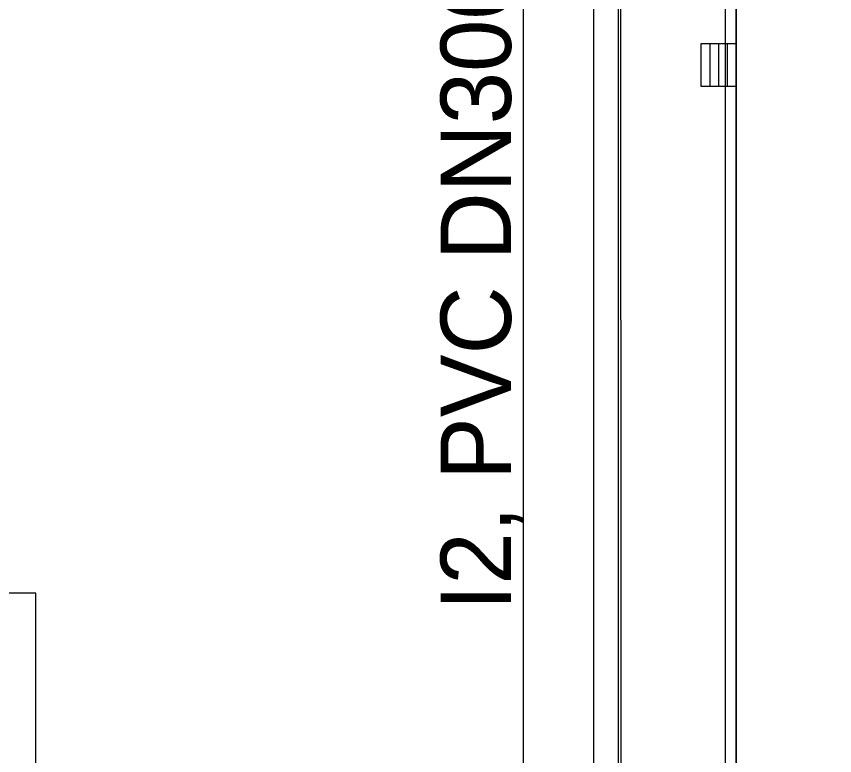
# Model space of a CAD drawing. Extents: x -264234 to -263604, y -1242346 to -1242049.
# Drawn here: x -263832.36 to -263809.12, y -1242205 to -1242184 of the extents above; entities that cross this region are included whole.
import ezdxf

# ---------------------------------------------------------------- set-up
doc = ezdxf.new("R2010")
doc.units = 0
for name, color, linetype in [('KFA_DAZDOVA_KANALIZACIA_vetva_I', 7, 'Continuous'), ('KFA_DAZDOVA_KANALIZACIA_vetva_I_popis', 7, 'Continuous'), ('KFA_SITUACIA_DSP', 7, 'Continuous')]:
    doc.layers.add(name, color=color, linetype=linetype)

msp = doc.modelspace()

# ---------------------------------------------------------------- linework, layer by layer
at = {"layer": 'KFA_DAZDOVA_KANALIZACIA_vetva_I'}
msp.add_lwpolyline([(-263814.907, -1242107.856), (-263815.198, -1242164.443), (-263815.189, -1242220.791), (-263852.152, -1242220.736), (-263888.701, -1242220.786), (-263906.731, -1242239.259)], dxfattribs=at)
at = {"layer": 'KFA_SITUACIA_DSP'}
for p, q in [((-263815.263, -1242164.687), (-263815.263, -1242220.396)), ((-263811.918, -1242184.782), (-263812.918, -1242184.782)), ((-263812.918, -1242184.782), (-263812.918, -1242185.982)), ((-263812.668, -1242184.782), (-263812.668, -1242185.982)), ((-263812.418, -1242184.782), (-263812.418, -1242185.982)), ((-263812.168, -1242184.782), (-263812.168, -1242185.982)), ((-263812.918, -1242185.982), (-263811.918, -1242185.982))]:
    msp.add_line(p, q, dxfattribs=at)
for points in [[(-263816.02, -1242224.432), (-263811.918, -1242220.33), (-263811.918, -1242108.434), (-263816.02, -1242104.332), (-263887.916, -1242104.332), (-263892.018, -1242108.434), (-263892.018, -1242147.332), (-263893.618, -1242147.332), (-263893.618, -1242162.382), (-263894.718, -1242162.382), (-263894.718, -1242166.382), (-263893.618, -1242166.382), (-263893.618, -1242181.432), (-263892.018, -1242181.432), (-263892.018, -1242220.33), (-263887.916, -1242224.432)], [(-263816.144, -1242224.132), (-263812.218, -1242220.206), (-263812.218, -1242108.558), (-263816.144, -1242104.632), (-263887.792, -1242104.632), (-263891.718, -1242108.558), (-263891.718, -1242147.632), (-263893.318, -1242147.632), (-263893.318, -1242162.682), (-263894.418, -1242162.682), (-263894.418, -1242166.082), (-263893.318, -1242166.082), (-263893.318, -1242181.132), (-263891.718, -1242181.132), (-263891.718, -1242220.206), (-263887.792, -1242224.132)], [(-263887.968, -1242108.434), (-263815.968, -1242108.434), (-263815.968, -1242220.33), (-263887.968, -1242220.33)], [(-263885.968, -1242111.882), (-263817.968, -1242111.882), (-263817.968, -1242216.882), (-263885.968, -1242216.882)], [(-263831.808, -1242200.382), (-263872.128, -1242200.382), (-263872.128, -1242216.882), (-263831.808, -1242216.882)]]:
    msp.add_lwpolyline(points, close=True, dxfattribs=at)
msp.add_lwpolyline([(-263811.918, -1242108.434), (-263811.918, -1242220.33), (-263812.262, -1242220.675), (-263809.862, -1242221.669), (-263810.999, -1242222.806), (-263807.039, -1242226.765), (-263809.585, -1242229.311), (-263813.545, -1242225.351), (-263814.681, -1242226.488), (-263815.675, -1242224.088), (-263816.02, -1242224.432), (-263887.916, -1242224.432), (-263888.26, -1242224.088), (-263889.254, -1242226.488), (-263890.391, -1242225.351), (-263894.351, -1242229.311), (-263896.896, -1242226.765), (-263892.937, -1242222.806), (-263894.073, -1242221.669), (-263891.673, -1242220.675), (-263892.018, -1242220.33), (-263892.018, -1242181.432), (-263893.618, -1242181.432), (-263893.618, -1242147.332)], dxfattribs=at)

# ---------------------------------------------------------------- texts
at = {"layer": 'KFA_DAZDOVA_KANALIZACIA_vetva_I_popis'}
msp.add_text('I2, PVC DN300 - 56,35 m', height=2, rotation=90, dxfattribs=at).set_placement((-263818.311, -1242200.884))

doc.saveas('drawing.dxf')
